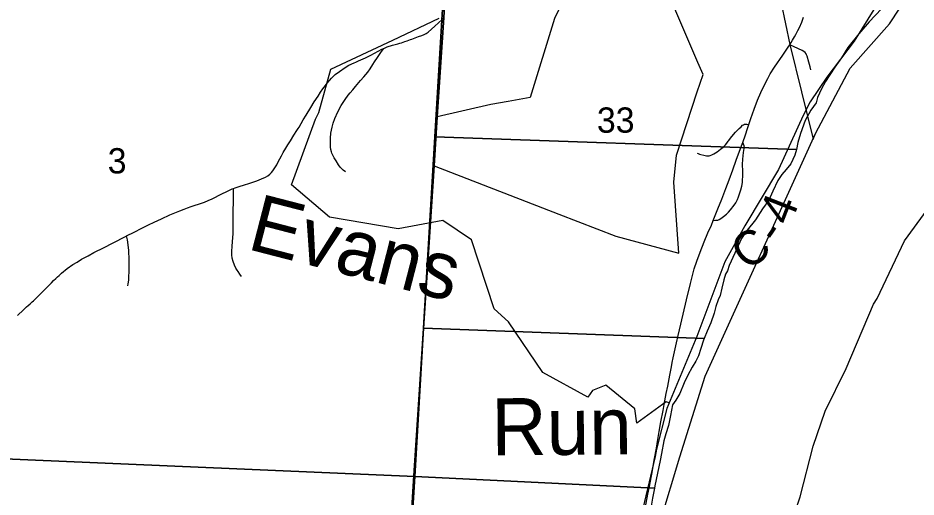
# Model space of a CAD drawing. Extents: x 0 to 34, y 0 to 22.
# Drawn here: x 26.889 to 28.376, y 17.925 to 18.718 of the extents above; entities that cross this region are included whole.
import ezdxf

# ---------------------------------------------------------------- set-up
doc = ezdxf.new("R2010")
doc.units = 0
for name, color, linetype in [('Default', 7, 'Continuous'), ('GM_X_City_Street', 7, 'Continuous'), ('GM_X_County_Road', 7, 'Continuous'), ('GM_X_County_Road_Text', 7, 'Continuous'), ('GM_X_Major_River', 7, 'Continuous'), ('GM_X_Minor_River', 7, 'Continuous'), ('GM_X_Minor_River_Text', 7, 'Continuous'), ('GM_X_Section', 7, 'Continuous'), ('GM_X_Section_Text', 7, 'Continuous'), ('GM_X_State_Route', 7, 'Continuous'), ('GM_X_Township_Road', 7, 'Continuous'), ('SH_Text', 7, 'Continuous')]:
    doc.layers.add(name, color=color, linetype=linetype)

msp = doc.modelspace()

# ---------------------------------------------------------------- linework, layer by layer
at = {"layer": 'Default'}
for points in [[(27.477, 16.8624), (27.5436, 17.9511), (27.5778, 18.4732), (27.5831, 18.5542), (27.5939, 18.7192), (27.6065, 18.9313), (27.6117, 19.011), (27.6573, 19.7849), (27.6577, 19.7927), (27.658, 19.8018), (27.6584, 19.8127), (27.6591, 19.8289), (27.6592, 19.8432), (27.6592, 19.8474), (27.6594, 19.8586), (27.6594, 19.8591), (27.6594, 19.8627), (27.6594, 19.867), (27.6595, 19.8705), (27.6597, 19.8748), (27.6605, 19.8792), (27.7198, 20.9), (23.5167, 20.9)], [(30.3167, 20.9), (27.7198, 20.9), (27.6605, 19.8792), (27.6597, 19.8748), (27.6595, 19.8705), (27.6594, 19.867), (27.6594, 19.8627), (27.6594, 19.8591), (27.6594, 19.8586), (27.6592, 19.8474), (27.6592, 19.8432), (27.6591, 19.8289), (27.6584, 19.8127), (27.658, 19.8018), (27.6577, 19.7927), (27.6573, 19.7849), (27.6117, 19.011), (27.6065, 18.9313), (27.5939, 18.7192), (27.5831, 18.5542), (27.5778, 18.4732), (27.5436, 17.9511), (27.477, 16.8624)], [(27.9525, 17.8831), (27.9847, 17.9912), (28.0266, 18.1245), (28.2096, 18.5267), (28.267, 18.6353), (28.332, 18.7085), (28.3661, 18.7612), (28.4364, 18.8208), (28.4791, 18.8705), (28.6246, 18.9977), (28.8094, 19.1502), (28.879, 19.2086), (29.0192, 19.305), (29.2694, 19.4948), (29.3261, 19.5426), (29.4248, 19.6871), (29.5488, 19.8131), (29.644, 19.878), (29.7344, 19.9057), (29.8761, 19.9228), (30.0125, 19.9577)], [(28.1238, 18.8801), (28.1668, 18.6742), (28.2054, 18.5176), (28.2096, 18.5267), (28.267, 18.6353), (28.332, 18.7085), (28.3661, 18.7612)], [(27.7843, 18.7324), (27.7771, 18.7171), (27.7371, 18.5862), (27.7007, 18.5798), (27.6718, 18.5747), (27.5831, 18.5542), (27.5778, 18.4732), (27.7844, 18.3929), (27.8788, 18.3567), (27.9829, 18.3288), (27.9747, 18.4459), (27.9794, 18.4911), (28.0134, 18.5958), (28.0232, 18.6243), (28.0144, 18.6442), (27.9732, 18.7411)]]:
    msp.add_lwpolyline(points, dxfattribs=at)
at = {"layer": 'GM_X_City_Street'}
msp.add_lwpolyline([(28.2018, 18.6321), (28.2004, 18.6375), (28.1983, 18.6451), (28.1955, 18.6548), (28.1947, 18.6573), (28.1938, 18.6589), (28.1922, 18.6608), (28.1899, 18.6628), (28.1873, 18.6644), (28.1739, 18.6705), (28.167, 18.6736)], dxfattribs=at)
at = {"layer": 'GM_X_County_Road'}
for points in [[(26.8879, 18.2254), (26.8982, 18.2348), (26.9, 18.2365), (26.9032, 18.2395), (26.906, 18.2419), (26.9091, 18.2448), (26.9123, 18.2477), (26.9146, 18.2498), (26.9177, 18.2528), (26.9212, 18.2563), (26.9239, 18.2588), (26.9274, 18.2623), (26.9305, 18.2654), (26.9339, 18.2689), (26.9375, 18.2724), (26.9409, 18.276), (26.9444, 18.2794), (26.9479, 18.283), (26.9515, 18.2863), (26.9546, 18.2893), (26.9574, 18.2918), (26.961, 18.2952), (26.9706, 18.3032), (26.9798, 18.3095), (26.9869, 18.3139), (26.9941, 18.3184), (26.9984, 18.3207), (27.005, 18.3244), (27.0146, 18.3296), (27.0314, 18.3382), (27.0454, 18.3451), (27.0679, 18.3568), (27.0688, 18.3573), (27.0814, 18.3634), (27.0938, 18.3699), (27.1051, 18.3756), (27.1142, 18.3799), (27.1266, 18.3857), (27.1404, 18.3919), (27.1571, 18.3988), (27.164, 18.4014), (27.1698, 18.4036), (27.1758, 18.4057), (27.1809, 18.4073), (27.1897, 18.4101), (27.1978, 18.4131), (27.2037, 18.4156), (27.2103, 18.4184), (27.2161, 18.4215), (27.2212, 18.4241), (27.2273, 18.4272), (27.2334, 18.4302), (27.2383, 18.4324), (27.2437, 18.4349), (27.2459, 18.4357), (27.2485, 18.4366), (27.2554, 18.439), (27.2641, 18.4419), (27.2714, 18.4442), (27.2843, 18.4485), (27.2924, 18.4516), (27.2986, 18.4543), (27.3027, 18.4567), (27.3059, 18.4593), (27.3087, 18.4621), (27.3111, 18.4652), (27.3132, 18.4682), (27.3175, 18.475), (27.32, 18.4799), (27.325, 18.4899), (27.328, 18.4953), (27.3322, 18.5023), (27.3358, 18.5081), (27.3401, 18.5149), (27.3458, 18.5238), (27.3507, 18.5317), (27.352, 18.5337), (27.3529, 18.5353), (27.3543, 18.5373), (27.3613, 18.5497), (27.3659, 18.5571), (27.3738, 18.5696), (27.3793, 18.579), (27.3859, 18.5888), (27.39, 18.595), (27.3937, 18.6007), (27.3959, 18.6038), (27.4007, 18.6103), (27.4078, 18.6182), (27.4142, 18.6243), (27.4211, 18.6297), (27.4304, 18.636), (27.4369, 18.6398), (27.4453, 18.6439), (27.4482, 18.6451), (27.4526, 18.647), (27.4567, 18.6487), (27.4643, 18.6521), (27.4729, 18.6563), (27.4794, 18.66), (27.4853, 18.6633), (27.4914, 18.6664), (27.4945, 18.6678), (27.4958, 18.6684), (27.5002, 18.6702), (27.5089, 18.6731), (27.5177, 18.6754), (27.5214, 18.6763), (27.5239, 18.677), (27.5268, 18.678), (27.5297, 18.679), (27.5332, 18.6802), (27.539, 18.6823), (27.5413, 18.6833), (27.5465, 18.6853), (27.5522, 18.6875), (27.5575, 18.6894), (27.5616, 18.6909), (27.5647, 18.6927), (27.568, 18.6947), (27.5793, 18.7044), (27.5915, 18.7157), (27.5941, 18.7186)], [(28.0402, 18.3828), (28.0437, 18.383), (28.0461, 18.3832), (28.0475, 18.3834), (28.0499, 18.3843), (28.0525, 18.3859), (28.0571, 18.3891), (28.0619, 18.393), (28.0654, 18.3965), (28.0686, 18.4002), (28.0748, 18.408), (28.0775, 18.4121), (28.0803, 18.4177), (28.082, 18.4217), (28.0859, 18.4335), (28.0874, 18.4395), (28.0884, 18.4456), (28.0888, 18.4499), (28.0889, 18.4555), (28.0889, 18.4616), (28.0888, 18.4783), (28.0889, 18.4814), (28.0891, 18.4838), (28.0898, 18.4906), (28.091, 18.4993), (28.0916, 18.5038), (28.0911, 18.5061), (28.0889, 18.512)]]:
    msp.add_lwpolyline(points, dxfattribs=at)
at = {"layer": 'GM_X_Major_River'}
for points in [[(28.4585, 18.8968), (28.4362, 18.8796), (28.3903, 18.835), (28.3545, 18.795), (28.309, 18.7367), (28.2733, 18.68), (28.2282, 18.6202), (28.2004, 18.5791), (28.1888, 18.5567), (28.1483, 18.4669), (28.0924, 18.3741), (28.0593, 18.314), (28.013, 18.1904), (27.9635, 18.0714), (27.946, 18.0041), (27.9438, 17.9919), (27.9185, 17.8844)], [(28.1677, 17.8763), (28.1838, 17.9246), (28.2057, 18.0086), (28.2255, 18.0667), (28.26, 18.1375), (28.3053, 18.244), (28.3113, 18.2535), (28.3567, 18.349), (28.4319, 18.4518)]]:
    msp.add_lwpolyline(points, dxfattribs=at)
at = {"layer": 'GM_X_Minor_River'}
msp.add_lwpolyline([(27.9671, 18.0806), (27.9619, 18.0824), (27.9134, 18.0467), (27.9104, 18.0705), (27.8621, 18.11), (27.8402, 18.101), (27.8323, 18.09), (27.7578, 18.1311), (27.7012, 18.2148), (27.6774, 18.2362), (27.6399, 18.3509), (27.5924, 18.3827), (27.5185, 18.3688), (27.4048, 18.3883), (27.3418, 18.4416), (27.3814, 18.5505), (27.3869, 18.5616), (27.4072, 18.6335), (27.5095, 18.6815), (27.5861, 18.7178)], dxfattribs=at)
at = {"layer": 'GM_X_Section'}
for points in [[(26.5652, 19.0298), (27.6061, 18.9865), (27.5941, 18.7705), (27.5794, 18.5214), (27.5606, 18.2043), (27.546, 17.9583), (26.4949, 18.0036), (26.551, 18.7947)], [(28.3268, 18.7428), (28.3189, 18.7336), (28.2982, 18.7119), (28.2812, 18.6921), (28.2631, 18.6693), (28.2522, 18.6519), (28.2416, 18.6367), (28.2329, 18.6241), (28.2258, 18.6131), (28.2194, 18.601), (28.213, 18.5862), (28.2104, 18.5778), (28.2017, 18.5653), (28.1923, 18.5486), (28.1844, 18.5266), (28.1799, 18.5118), (28.1777, 18.5002), (27.5794, 18.5214), (27.5941, 18.7705)], [(27.5794, 18.5214), (28.1777, 18.5002), (28.175, 18.491), (28.1687, 18.4765), (28.1611, 18.467), (28.1539, 18.4587), (28.1468, 18.4492), (28.1389, 18.4313), (28.1321, 18.4162), (28.1219, 18.4021), (28.1099, 18.3839), (28.0963, 18.3664), (28.0869, 18.3531), (28.076, 18.3284), (28.0662, 18.308), (28.0636, 18.2992), (28.0605, 18.2935), (28.0576, 18.2841), (28.0546, 18.2704), (28.0516, 18.2583), (28.0482, 18.2514), (28.0444, 18.2401), (28.0415, 18.2291), (28.0362, 18.2131), (28.0302, 18.1991), (28.025, 18.1872), (27.5606, 18.2043)], [(28.025, 18.1872), (28.0238, 18.1843), (28.0197, 18.1706), (28.0156, 18.1585), (28.0114, 18.1494), (28.0054, 18.1395), (27.9982, 18.1262), (27.9918, 18.1137), (27.9847, 18.0963), (27.9779, 18.0852), (27.9726, 18.0773), (27.9693, 18.0598), (27.9659, 18.0431), (27.9618, 18.0295), (27.9584, 18.0177), (27.9544, 17.9969), (27.9521, 17.9851), (27.9476, 17.9639), (27.9436, 17.943), (27.9429, 17.9393), (27.546, 17.9583), (27.5606, 18.2043)], [(26.4949, 18.0036), (27.546, 17.9583), (27.5355, 17.7931), (27.4974, 17.1618), (27.484, 16.9363), (26.4248, 16.9831)], [(27.9429, 17.9393), (27.9398, 17.9229), (27.9365, 17.9029), (27.9339, 17.8805), (27.9321, 17.8555), (27.9307, 17.8297), (27.9288, 17.8149), (27.9278, 17.8001), (27.9267, 17.7785), (27.5355, 17.7931), (27.546, 17.9583)]]:
    msp.add_lwpolyline(points, close=True, dxfattribs=at)
at = {"layer": 'GM_X_State_Route'}
for points in [[(28.167, 18.6736), (28.1715, 18.6812), (28.1748, 18.6868), (28.1769, 18.6909), (28.1803, 18.6974), (28.1828, 18.7025), (28.1868, 18.7115), (28.1898, 18.7196)], [(28.1563, 18.6583), (28.1643, 18.6697), (28.167, 18.6736)], [(27.9251, 17.8934), (27.9319, 17.9294), (27.9346, 17.9422), (27.9358, 17.9483), (27.9385, 17.9623), (27.943, 17.9886), (27.9459, 18.0057), (27.9478, 18.0167), (27.9508, 18.0332), (27.9536, 18.0491), (27.9571, 18.0681), (27.959, 18.0778), (27.9624, 18.0962), (27.9647, 18.1084), (27.9681, 18.1267), (27.9708, 18.1401), (27.9723, 18.1473), (27.974, 18.1552), (27.9793, 18.1801), (27.9819, 18.1922), (27.9863, 18.211), (27.996, 18.2515), (28.0022, 18.2781), (28.0056, 18.2913), (28.0088, 18.3027), (28.0128, 18.3152), (28.0183, 18.3304), (28.025, 18.3472), (28.0313, 18.3621), (28.0371, 18.3751), (28.0402, 18.3828), (28.0424, 18.3884), (28.0479, 18.4022), (28.0541, 18.4178), (28.0611, 18.4357), (28.0665, 18.4503), (28.0724, 18.4666), (28.0781, 18.4824), (28.0868, 18.5063), (28.0889, 18.512), (28.0934, 18.5244), (28.097, 18.535), (28.0993, 18.5419), (28.1025, 18.5515), (28.1081, 18.5673), (28.1136, 18.5819), (28.1189, 18.5945), (28.125, 18.6075), (28.1304, 18.618), (28.1346, 18.6257), (28.1416, 18.6367), (28.1552, 18.6567), (28.1563, 18.6583)]]:
    msp.add_lwpolyline(points, dxfattribs=at)
at = {"layer": 'GM_X_Township_Road'}
for points in [[(27.4078, 18.4967), (27.4072, 18.5002), (27.4066, 18.5039), (27.4063, 18.5107), (27.4064, 18.5188), (27.4072, 18.5274), (27.4089, 18.5372), (27.4106, 18.5438), (27.4137, 18.5519), (27.4187, 18.5626), (27.4243, 18.573), (27.4305, 18.5831), (27.4355, 18.5901), (27.439, 18.5943), (27.4431, 18.5992), (27.4479, 18.6049), (27.4506, 18.6082), (27.4562, 18.6148), (27.4614, 18.6208), (27.468, 18.6285), (27.4722, 18.6339), (27.4767, 18.6412), (27.4795, 18.6456), (27.4841, 18.6527), (27.4908, 18.6624), (27.4945, 18.6678)], [(28.0137, 18.4943), (28.0152, 18.4934), (28.0175, 18.4926), (28.027, 18.4903), (28.0288, 18.4899), (28.0312, 18.4896), (28.0331, 18.4897), (28.0348, 18.4901), (28.0377, 18.4912), (28.0411, 18.4931), (28.0466, 18.4967), (28.0524, 18.501), (28.0544, 18.5025), (28.0563, 18.5041), (28.058, 18.5056), (28.0589, 18.5064), (28.0604, 18.5081), (28.0627, 18.5109), (28.0636, 18.5122), (28.065, 18.514), (28.0659, 18.5153), (28.0687, 18.519), (28.0738, 18.5253), (28.077, 18.5289), (28.0782, 18.5303), (28.0829, 18.5349), (28.0863, 18.5381), (28.0888, 18.5404), (28.0903, 18.5414), (28.0917, 18.5421), (28.0937, 18.5425), (28.0955, 18.5425), (28.0993, 18.5419)], [(27.431, 18.4631), (27.4275, 18.466), (27.4251, 18.4683), (27.4226, 18.4712), (27.4198, 18.4749), (27.4156, 18.4814), (27.4122, 18.4865), (27.41, 18.4908), (27.4086, 18.4944), (27.4078, 18.4967)], [(27.2591, 18.2898), (27.256, 18.294), (27.2535, 18.2979), (27.2518, 18.3003), (27.2506, 18.3023), (27.2497, 18.3039), (27.2476, 18.3084), (27.2452, 18.3148), (27.2438, 18.3202), (27.2431, 18.3257), (27.243, 18.3319), (27.2434, 18.3394), (27.2441, 18.348), (27.2451, 18.3603), (27.2453, 18.3717), (27.2454, 18.3814), (27.2452, 18.3906), (27.2453, 18.3974), (27.246, 18.4147), (27.2459, 18.4289), (27.2459, 18.4357)], [(27.071, 18.2743), (27.0716, 18.2777), (27.0721, 18.2807), (27.0724, 18.2844), (27.0728, 18.3032), (27.0729, 18.3175), (27.0724, 18.333), (27.0716, 18.3422), (27.07, 18.3508), (27.0688, 18.3573)]]:
    msp.add_lwpolyline(points, dxfattribs=at)
at = {"layer": 'SH_Text'}
msp.add_lwpolyline([(27.9525, 17.8831), (27.9847, 17.9912), (28.0266, 18.1245), (28.2096, 18.5267), (28.267, 18.6353), (28.332, 18.7085), (28.3661, 18.7612), (28.4364, 18.8208), (28.4791, 18.8705), (28.6246, 18.9977), (28.8094, 19.1502), (28.879, 19.2086), (29.0192, 19.305), (29.2694, 19.4948), (29.3261, 19.5426), (29.4248, 19.6871), (29.5488, 19.8131), (29.644, 19.878), (29.7344, 19.9057), (29.8761, 19.9228), (30.0125, 19.9577)], dxfattribs=at)

# ---------------------------------------------------------------- texts
at = {"layer": 'GM_X_County_Road_Text'}
for s, rotation, p in [('4', 68.6685, (28.1674, 18.3723)), ('C', 37.3937, (28.0971, 18.298)), ('-', 55.695, (28.1477, 18.3407))]:
    msp.add_text(s, height=0.0568, rotation=rotation, dxfattribs=at).set_placement(p)
at = {"layer": 'GM_X_Minor_River_Text'}
for s, rotation, p in [('Evans', 345.5114, (27.2663, 18.3359)), ('Run', 0.5113, (27.6732, 17.9933))]:
    msp.add_text(s, height=0.0947, rotation=rotation, dxfattribs=at).set_placement(p)
at = {"layer": 'GM_X_Section_Text'}
for s, height, p in [('33', 0.04186, (27.8475, 18.5281)), ('3', 0.0419, (27.0375, 18.4606))]:
    msp.add_text(s, height=height, rotation=0, dxfattribs=at).set_placement(p)

doc.saveas('drawing.dxf')
